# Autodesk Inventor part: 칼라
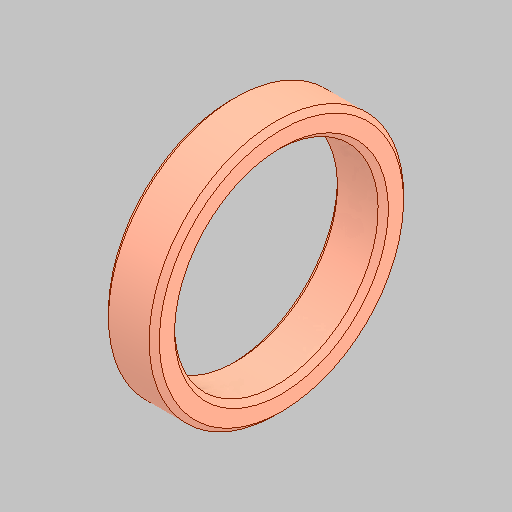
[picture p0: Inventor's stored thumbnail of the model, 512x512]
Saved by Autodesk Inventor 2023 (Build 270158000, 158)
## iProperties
Created: 2025-09
Part Number: 칼라
Material: 강철, 연강
Document SubType Name: Modeling
Designer: home
Density: 7.85 g/cm^3
Appearance: 기본값
Author: jhkim
Sending System: Autodesk Inventor 2026
Preprocessor: ST-DEVELOPER v20.1
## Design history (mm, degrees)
feature "솔리드1"
node "솔리드2"
